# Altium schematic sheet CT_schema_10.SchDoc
size 274 x 160 mm
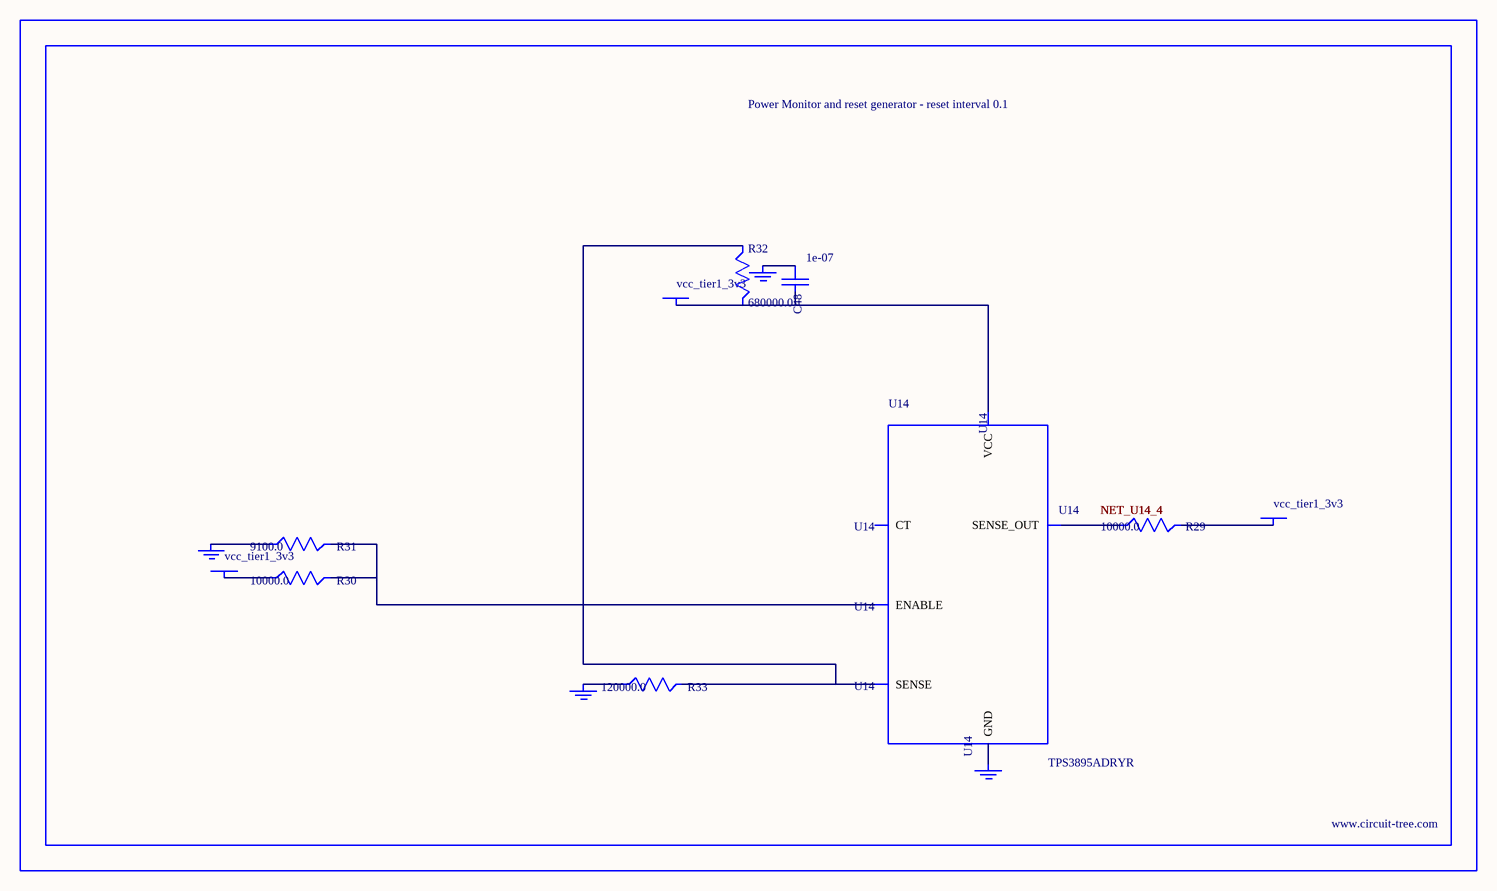
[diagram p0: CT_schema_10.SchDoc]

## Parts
BORDER9  (no value)
C48  1e-07  [C0402]
GND_INSTANCE_9_0  (no value)
GND_INSTANCE_9_1  (no value)
GND_INSTANCE_9_2  (no value)
GND_INSTANCE_9_3  (no value)
POWER_INSTANCE_9_0  vcc_tier1_3v3
POWER_INSTANCE_9_1  vcc_tier1_3v3
POWER_INSTANCE_9_2  vcc_tier1_3v3
R29  10000.0  [R0603]
R30  10000.0  [R0603]
R31  9100.0  [R0603]
R32  680000.0  [R0603]
R33  120000.0  [R0603]
U14  TPS3895ADRYR  [SON-6]

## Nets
NetC48_1: C48.1 GND_INSTANCE_9_2.0(GND)
NetC48_2: C48.2 POWER_INSTANCE_9_2.0(PWR) R32.2 U14.6(VCC)
NetGND_INSTANCE_9_0_0: GND_INSTANCE_9_0.0(GND) R31.1
NetGND_INSTANCE_9_1_0: GND_INSTANCE_9_1.0(GND) R33.1
NetGND_INSTANCE_9_3_0: GND_INSTANCE_9_3.0(GND) U14.2(GND)
NetPOWER_INSTANCE_9_0_0: POWER_INSTANCE_9_0.0(PWR) R30.1
NetPOWER_INSTANCE_9_1_0: POWER_INSTANCE_9_1.0(PWR) R29.2
NetR29_1: R29.1 U14.4(SENSE_OUT)
NetR30_2: R30.2 R31.2 U14.1(ENABLE)
NetR32_1: R32.1 R33.2 U14.3(SENSE)

Not connected (* = marked no-connect by the designer): U14 5(CT)

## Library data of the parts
BORDER9 = BORDER_PAGE9
C48 = C0402C104K3RACTU
GND_INSTANCE_9_0-GND_INSTANCE_9_3 = GND
POWER_INSTANCE_9_0-POWER_INSTANCE_9_2 = PWR
R29 R30 = RC0603JR-0710KL
R31 = RC0603JR-079K1L
R32 = RC0603JR-07680KL
R33 = RC0603JR-07120KL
